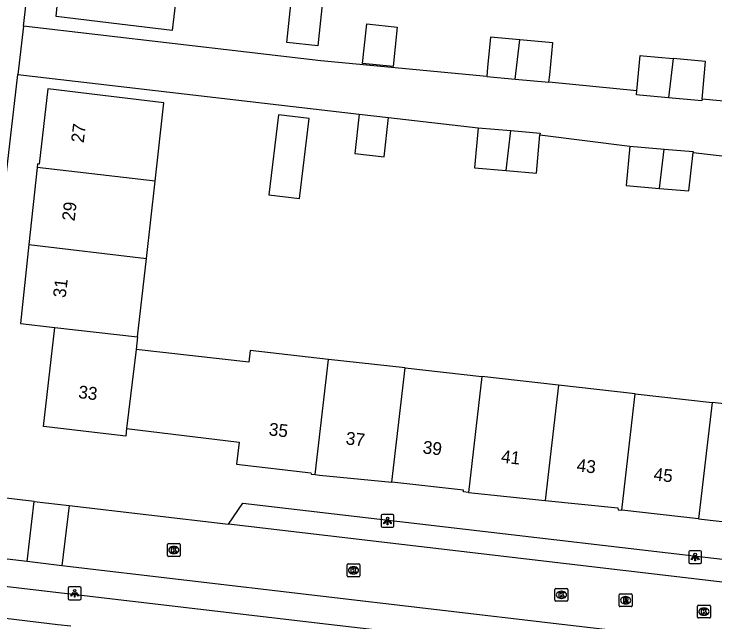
# Model space of a CAD drawing. Extents: x 161243 to 161752, y 384138 to 384885.
# Drawn here: x 161353.3 to 161408.1, y 384500.2 to 384547.7 of the extents above; entities that cross this region are included whole.
import ezdxf

# ---------------------------------------------------------------- set-up
doc = ezdxf.new("R2010")
doc.units = 0
for name, color, linetype in [('IMGEO_Kolk', 7, 'Continuous'), ('IMGEO_Lichtpunt', 7, 'Continuous'), ('IMGEO_Pand', 7, 'Continuous'), ('IMGEO_Pand_nummerreeks', 7, 'Continuous'), ('IMGEO_Parkeervlak_open', 7, 'Continuous'), ('IMGEO_Rijbaan_lokaal_open', 7, 'Continuous'), ('IMGEO_Rioolput', 7, 'Continuous'), ('IMGEO_Voetpad_open', 7, 'Continuous')]:
    doc.layers.add(name, color=color, linetype=linetype)

msp = doc.modelspace()

# ---------------------------------------------------------------- linework, layer by layer
at = {"layer": 'IMGEO_Kolk'}
for p, q in [((161365.337, 384505.38), (161365.337, 384506.232)), ((161365.412, 384506.306), (161366.264, 384506.306)), ((161365.825, 384506.086), (161365.85, 384506.086)), ((161366.338, 384506.232), (161366.338, 384505.38)), ((161366.264, 384505.306), (161365.412, 384505.306)), ((161365.848, 384505.526), (161365.823, 384505.526)), ((161379.458, 384504.718), (161380.31, 384504.718)), ((161379.383, 384503.792), (161379.383, 384504.644)), ((161379.871, 384504.498), (161379.896, 384504.498)), ((161380.384, 384504.644), (161380.384, 384503.792)), ((161380.31, 384503.718), (161379.458, 384503.718)), ((161379.894, 384503.938), (161379.869, 384503.938)), ((161395.629, 384501.882), (161395.629, 384502.734)), ((161395.704, 384502.808), (161396.556, 384502.808)), ((161396.117, 384502.588), (161396.142, 384502.588)), ((161396.63, 384502.734), (161396.63, 384501.882)), ((161396.14, 384502.028), (161396.115, 384502.028)), ((161396.556, 384501.808), (161395.704, 384501.808)), ((161406.773, 384500.574), (161406.773, 384501.426)), ((161406.848, 384501.5), (161407.7, 384501.5)), ((161407.774, 384501.426), (161407.774, 384500.574)), ((161407.261, 384501.28), (161407.286, 384501.28)), ((161407.7, 384500.5), (161406.848, 384500.5)), ((161407.284, 384500.72), (161407.259, 384500.72))]:
    msp.add_line(p, q, dxfattribs=at)
for points in [[(161365.337, 384505.38), (161365.337, 384506.232)], [(161365.412, 384506.306), (161366.264, 384506.306)], [(161365.658, 384506.006), (161365.781, 384506.006), (161365.781, 384505.855), (161365.911, 384506.006), (161366.075, 384506.006), (161365.929, 384505.855), (161366.082, 384505.606), (161365.93, 384505.606), (161365.845, 384505.77), (161365.781, 384505.703), (161365.781, 384505.606), (161365.658, 384505.606), (161365.658, 384506.006)], [(161366.338, 384506.232), (161366.338, 384505.38)], [(161366.264, 384505.306), (161365.412, 384505.306)], [(161379.458, 384504.718), (161380.31, 384504.718)], [(161379.383, 384503.792), (161379.383, 384504.644)], [(161379.704, 384504.418), (161379.827, 384504.418), (161379.827, 384504.267), (161379.957, 384504.418), (161380.121, 384504.418), (161379.975, 384504.267), (161380.128, 384504.018), (161379.976, 384504.018), (161379.891, 384504.182), (161379.827, 384504.115), (161379.827, 384504.018), (161379.704, 384504.018), (161379.704, 384504.418)], [(161380.384, 384504.644), (161380.384, 384503.792)], [(161380.31, 384503.718), (161379.458, 384503.718)], [(161395.629, 384501.882), (161395.629, 384502.734)], [(161395.704, 384502.808), (161396.556, 384502.808)], [(161395.95, 384502.508), (161396.073, 384502.508), (161396.073, 384502.357), (161396.203, 384502.508), (161396.367, 384502.508), (161396.221, 384502.357), (161396.374, 384502.108), (161396.222, 384502.108), (161396.137, 384502.272), (161396.073, 384502.205), (161396.073, 384502.108), (161395.95, 384502.108), (161395.95, 384502.508)], [(161396.63, 384502.734), (161396.63, 384501.882)], [(161396.556, 384501.808), (161395.704, 384501.808)], [(161406.773, 384500.574), (161406.773, 384501.426)], [(161406.848, 384501.5), (161407.7, 384501.5)], [(161407.774, 384501.426), (161407.774, 384500.574)], [(161407.094, 384501.2), (161407.217, 384501.2), (161407.217, 384501.049), (161407.347, 384501.2), (161407.511, 384501.2), (161407.365, 384501.049), (161407.518, 384500.8), (161407.366, 384500.8), (161407.281, 384500.964), (161407.217, 384500.897), (161407.217, 384500.8), (161407.094, 384500.8), (161407.094, 384501.2)], [(161407.7, 384500.5), (161406.848, 384500.5)]]:
    msp.add_lwpolyline(points, dxfattribs=at)
for centre, start, end in [((161365.414, 384506.23), 91.552, 178.448), ((161365.414, 384506.23), 91.552, 178.448), ((161366.262, 384506.23), 1.552, 88.448), ((161366.262, 384506.23), 1.552, 88.448), ((161365.414, 384505.382), 181.552, 268.448), ((161365.414, 384505.382), 181.552, 268.448), ((161366.262, 384505.382), 271.552, 358.448), ((161366.262, 384505.382), 271.552, 358.448), ((161379.46, 384504.642), 91.552, 178.448), ((161379.46, 384504.642), 91.552, 178.448), ((161380.308, 384504.642), 1.552, 88.448), ((161380.308, 384504.642), 1.552, 88.448), ((161379.46, 384503.794), 181.552, 268.448), ((161379.46, 384503.794), 181.552, 268.448), ((161380.308, 384503.794), 271.552, 358.448), ((161380.308, 384503.794), 271.552, 358.448), ((161395.706, 384502.732), 91.552, 178.448), ((161395.706, 384502.732), 91.552, 178.448), ((161396.554, 384502.732), 1.552, 88.448), ((161396.554, 384502.732), 1.552, 88.448), ((161395.706, 384501.884), 181.552, 268.448), ((161395.706, 384501.884), 181.552, 268.448), ((161396.554, 384501.884), 271.552, 358.448), ((161396.554, 384501.884), 271.552, 358.448), ((161406.85, 384501.424), 91.552, 178.448), ((161406.85, 384501.424), 91.552, 178.448), ((161407.698, 384501.424), 1.552, 88.448), ((161407.698, 384501.424), 1.552, 88.448), ((161406.85, 384500.576), 181.552, 268.448), ((161406.85, 384500.576), 181.552, 268.448), ((161407.698, 384500.576), 271.552, 358.448), ((161407.698, 384500.576), 271.552, 358.448)]:
    msp.add_arc(centre, 0.0765, start, end, dxfattribs=at)
for centre, major_axis, ratio, start_param, end_param in [((161365.824, 384505.806), (-0.387, 0.002), 0.722429, 4.712389, 7.853982), ((161365.849, 384505.806), (-0.39, 0.002), 0.717154, 1.570796, 4.712389), ((161379.87, 384504.218), (-0.387, 0.002), 0.722429, 4.712389, 7.853982), ((161379.895, 384504.218), (-0.39, 0.002), 0.717154, 1.570796, 4.712389), ((161396.116, 384502.308), (-0.387, 0.002), 0.722429, 4.712389, 7.853982), ((161396.141, 384502.308), (-0.39, 0.002), 0.717154, 1.570796, 4.712389), ((161407.26, 384501), (-0.387, 0.002), 0.722429, 4.712389, 7.853982), ((161407.285, 384501), (-0.39, 0.002), 0.717154, 1.570796, 4.712389)]:
    msp.add_ellipse(centre, major_axis=major_axis, ratio=ratio, start_param=start_param, end_param=end_param, dxfattribs=at)
at = {"layer": 'IMGEO_Lichtpunt'}
for p, q in [((161382.952, 384508.578), (161382.144, 384508.578)), ((161382.952, 384508.578), (161382.144, 384508.578)), ((161382.05, 384508.483), (161382.05, 384507.676)), ((161382.05, 384508.483), (161382.05, 384507.676)), ((161383.046, 384507.676), (161383.046, 384508.483)), ((161383.046, 384507.676), (161383.046, 384508.483)), ((161382.144, 384507.582), (161382.952, 384507.582)), ((161382.144, 384507.582), (161382.952, 384507.582)), ((161406.083, 384505.663), (161406.083, 384504.856)), ((161406.083, 384505.663), (161406.083, 384504.856)), ((161406.985, 384505.758), (161406.177, 384505.758)), ((161406.985, 384505.758), (161406.177, 384505.758)), ((161407.079, 384504.856), (161407.079, 384505.663)), ((161407.079, 384504.856), (161407.079, 384505.663)), ((161406.177, 384504.762), (161406.985, 384504.762)), ((161406.177, 384504.762), (161406.985, 384504.762)), ((161357.591, 384502.83), (161357.591, 384502.023)), ((161357.591, 384502.83), (161357.591, 384502.023)), ((161358.493, 384502.925), (161357.685, 384502.925)), ((161358.493, 384502.925), (161357.685, 384502.925)), ((161358.587, 384502.023), (161358.587, 384502.83)), ((161358.587, 384502.023), (161358.587, 384502.83)), ((161357.685, 384501.929), (161358.493, 384501.929)), ((161357.685, 384501.929), (161358.493, 384501.929))]:
    msp.add_line(p, q, dxfattribs=at)
for points in [[(161382.424, 384508.147), (161382.463, 384508.119), (161382.275, 384507.857), (161382.237, 384507.884), (161382.424, 384508.147)], [(161382.526, 384508.099), (161382.573, 384508.099), (161382.573, 384507.777), (161382.526, 384507.777), (161382.526, 384508.099)], [(161382.636, 384508.119), (161382.674, 384508.146), (161382.861, 384507.884), (161382.822, 384507.856), (161382.636, 384508.119)], [(161406.457, 384505.327), (161406.496, 384505.299), (161406.308, 384505.037), (161406.27, 384505.064), (161406.457, 384505.327)], [(161406.559, 384505.279), (161406.606, 384505.279), (161406.606, 384504.957), (161406.559, 384504.957), (161406.559, 384505.279)], [(161406.669, 384505.299), (161406.707, 384505.326), (161406.894, 384505.064), (161406.855, 384505.036), (161406.669, 384505.299)], [(161357.965, 384502.494), (161358.004, 384502.466), (161357.816, 384502.204), (161357.778, 384502.231), (161357.965, 384502.494)], [(161358.177, 384502.466), (161358.215, 384502.493), (161358.402, 384502.231), (161358.363, 384502.203), (161358.177, 384502.466)], [(161358.067, 384502.446), (161358.114, 384502.446), (161358.114, 384502.124), (161358.067, 384502.124), (161358.067, 384502.446)]]:
    msp.add_lwpolyline(points, dxfattribs=at)
for centre in [(161382.549, 384508.281), (161406.582, 384505.461), (161358.09, 384502.628)]:
    msp.add_circle(centre, 0.0994, dxfattribs=at)
for centre, start, end in [((161382.144, 384508.483), 90, 180), ((161382.144, 384508.483), 90, 180), ((161382.952, 384508.483), 0, 90), ((161382.952, 384508.483), 0, 90), ((161382.144, 384507.676), 180, 270), ((161382.144, 384507.676), 180, 270), ((161382.952, 384507.676), 270, 0), ((161382.952, 384507.676), 270, 360), ((161406.177, 384505.663), 90, 180), ((161406.177, 384505.663), 90, 180), ((161406.985, 384505.663), 0, 90), ((161406.985, 384505.663), 0, 90), ((161406.177, 384504.856), 180, 270), ((161406.177, 384504.856), 180, 270), ((161406.985, 384504.856), 270, 0), ((161406.985, 384504.856), 270, 360), ((161357.685, 384502.83), 90, 180), ((161357.685, 384502.83), 90, 180), ((161358.493, 384502.83), 0, 90), ((161358.493, 384502.83), 0, 90), ((161357.685, 384502.023), 180, 270), ((161357.685, 384502.023), 180, 270), ((161358.493, 384502.023), 270, 0), ((161358.493, 384502.023), 270, 360)]:
    msp.add_arc(centre, 0.0946, start, end, dxfattribs=at)
at = {"layer": 'IMGEO_Pand'}
for points in [[(161366.438, 384552.56), (161365.715, 384546.372), (161361.603, 384546.876), (161356.64, 384547.484), (161357.225, 384553.321), (161357.263, 384553.636)], [(161374.67, 384545.446), (161375.302, 384551.397), (161377.728, 384551.139), (161377.098, 384545.197), (161374.67, 384545.446)], [(161380.915, 384546.899), (161383.297, 384546.65), (161382.973, 384543.56), (161380.592, 384543.81), (161380.915, 384546.899)], [(161392.883, 384545.649), (161390.582, 384545.866), (161390.36, 384543.501), (161390.293, 384542.794)], [(161392.525, 384542.584), (161392.883, 384545.649)], [(161395.161, 384542.336), (161395.217, 384542.927), (161395.45, 384545.408), (161392.883, 384545.649)], [(161402.036, 384541.672), (161402.295, 384544.437), (161402.53, 384544.415), (161404.855, 384544.197)], [(161404.855, 384544.197), (161404.496, 384541.131)], [(161407.123, 384541.032), (161407.398, 384543.958), (161404.855, 384544.197)], [(161390.293, 384542.794), (161392.525, 384542.584)], [(161392.525, 384542.584), (161395.161, 384542.336)], [(161364.373, 384534.605), (161365.062, 384540.738), (161360.954, 384541.232), (161355.989, 384541.828), (161355.319, 384535.95), (161355.195, 384535.982), (161355.163, 384535.687)], [(161404.496, 384541.131), (161402.241, 384541.343), (161402.007, 384541.365), (161402.036, 384541.672)], [(161407.123, 384541.032), (161407.109, 384540.886), (161404.496, 384541.131)], [(161373.265, 384533.537), (161375.67, 384533.25), (161376.416, 384539.512), (161374.01, 384539.798), (161373.265, 384533.537)], [(161380.337, 384539.851), (161379.995, 384536.783), (161382.266, 384536.529), (161382.609, 384539.597)], [(161380.337, 384539.851), (161382.609, 384539.597)], [(161389.625, 384538.791), (161389.352, 384535.651), (161391.807, 384535.437)], [(161389.625, 384538.791), (161392.174, 384538.569)], [(161391.807, 384535.437), (161392.174, 384538.569)], [(161391.807, 384535.437), (161394.187, 384535.23), (161394.449, 384538.235)], [(161392.174, 384538.569), (161394.461, 384538.369), (161394.449, 384538.235)], [(161401.474, 384537.359), (161401.206, 384534.28), (161403.791, 384534.055)], [(161401.474, 384537.359), (161404.151, 384537.125)], [(161403.791, 384534.055), (161404.151, 384537.125)], [(161404.151, 384537.125), (161406.44, 384536.926), (161406.432, 384536.854)], [(161403.791, 384534.055), (161406.08, 384533.855), (161406.432, 384536.854)], [(161355.163, 384535.687), (161354.513, 384529.66)], [(161364.373, 384534.605), (161355.163, 384535.687)], [(161363.697, 384528.581), (161364.373, 384534.605)], [(161354.513, 384529.66), (161353.849, 384523.505), (161356.534, 384523.195)], [(161354.513, 384529.66), (161363.697, 384528.581)], [(161363.009, 384522.448), (161363.697, 384528.581)], [(161362.13, 384515.29), (161362.078, 384514.704), (161355.646, 384515.453), (161356.534, 384523.195)], [(161356.534, 384523.195), (161363.009, 384522.448)], [(161363.009, 384522.448), (161362.9, 384521.481)], [(161362.9, 384521.481), (161362.13, 384515.29)], [(161377.931, 384520.699), (161371.808, 384521.386), (161371.708, 384520.492), (161362.9, 384521.481)], [(161376.875, 384511.701), (161377.931, 384520.699)], [(161383.926, 384520.026), (161377.931, 384520.699)], [(161382.88, 384511.115), (161383.926, 384520.026)], [(161383.926, 384520.026), (161389.92, 384519.353)], [(161389.92, 384519.353), (161388.859, 384510.31)], [(161395.914, 384518.68), (161389.92, 384519.353)], [(161395.914, 384518.68), (161394.858, 384509.685)], [(161401.908, 384518.007), (161395.914, 384518.68)], [(161400.842, 384508.921), (161401.908, 384518.007)], [(161401.908, 384518.007), (161407.903, 384517.334)], [(161407.903, 384517.334), (161406.836, 384508.241)], [(161413.897, 384516.661), (161407.903, 384517.334)], [(161362.13, 384515.29), (161370.953, 384514.221), (161370.746, 384512.522), (161376.552, 384511.837), (161376.584, 384511.732), (161376.875, 384511.701)], [(161376.875, 384511.701), (161377.225, 384511.664), (161382.88, 384511.115)], [(161388.859, 384510.31), (161388.492, 384510.348), (161388.492, 384510.475), (161382.88, 384511.115)], [(161388.859, 384510.31), (161394.858, 384509.685)], [(161394.858, 384509.685), (161400.554, 384509.091), (161400.579, 384508.951), (161400.842, 384508.921)], [(161406.836, 384508.241), (161400.842, 384508.921)], [(161406.836, 384508.241), (161412.83, 384507.56)], [(161351.799, 384500.579), (161356.763, 384500), (161357.799, 384499.879)]]:
    msp.add_lwpolyline(points, dxfattribs=at)
at = {"layer": 'IMGEO_Parkeervlak_open'}
msp.add_lwpolyline([(161370.122, 384507.816), (161371.245, 384509.461), (161423.885, 384503.32), (161424.463, 384501.437)], dxfattribs=at)
at = {"layer": 'IMGEO_Rijbaan_lokaal_open'}
for points in [[(161414.97, 384570.779), (161411.359, 384540.633), (161407.123, 384541.032)], [(161354.08, 384546.72), (161353.642, 384542.948)], [(161390.293, 384542.794), (161377.34, 384544.021), (161354.08, 384546.72)], [(161353.642, 384542.948), (161380.337, 384539.851)], [(161402.036, 384541.672), (161395.161, 384542.336)], [(161382.609, 384539.597), (161389.625, 384538.791)], [(161394.449, 384538.235), (161401.474, 384537.359)], [(161406.432, 384536.854), (161419.21, 384535.381), (161421.738, 384535.09), (161421.212, 384528.819), (161423.722, 384528.608), (161426.026, 384528.384)], [(161354.929, 384509.609), (161349.844, 384510.209)], [(161354.376, 384504.9), (161354.929, 384509.609)], [(161354.929, 384509.609), (161357.65, 384509.288)], [(161357.65, 384509.288), (161357.097, 384504.581)], [(161357.65, 384509.288), (161370.122, 384507.816)], [(161424.463, 384501.437), (161370.122, 384507.816)], [(161354.376, 384504.9), (161340.82, 384506.489)], [(161357.097, 384504.581), (161354.376, 384504.9)], [(161427.321, 384496.383), (161396.178, 384500), (161357.097, 384504.581)]]:
    msp.add_lwpolyline(points, dxfattribs=at)
at = {"layer": 'IMGEO_Rioolput'}
for p, q in [((161400.653, 384501.46), (161400.653, 384502.312)), ((161400.728, 384502.386), (161401.58, 384502.386)), ((161401.141, 384502.166), (161401.166, 384502.166)), ((161401.654, 384502.312), (161401.654, 384501.46)), ((161401.164, 384501.606), (161401.139, 384501.606)), ((161401.58, 384501.386), (161400.728, 384501.386))]:
    msp.add_line(p, q, dxfattribs=at)
for points in [[(161400.653, 384501.46), (161400.653, 384502.312)], [(161400.728, 384502.386), (161401.58, 384502.386)], [(161401.242, 384502.084), (161400.99, 384502.086), (161400.99, 384501.686)], [(161401.168, 384502.005), (161401.114, 384502.005), (161401.114, 384501.924)], [(161401.654, 384502.312), (161401.654, 384501.46)], [(161400.99, 384501.686), (161401.114, 384501.686), (161401.114, 384501.848), (161401.125, 384501.848)], [(161401.114, 384501.924), (161401.166, 384501.924)], [(161401.172, 384501.819), (161401.243, 384501.686), (161401.383, 384501.686), (161401.318, 384501.812)], [(161401.58, 384501.386), (161400.728, 384501.386)]]:
    msp.add_lwpolyline(points, dxfattribs=at)
for centre, radius, start, end in [((161400.73, 384502.31), 0.0765, 91.552, 178.448), ((161400.73, 384502.31), 0.0765, 91.552, 178.448), ((161401.174, 384501.909), 0.0964, 77.0061, 93.1865), ((161401.188, 384501.966), 0.0378, 276.6634, 79.6772), ((161401.241, 384501.974), 0.109, 350.3612, 89.416), ((161401.239, 384501.974), 0.112, 277.5842, 350.9817), ((161401.578, 384502.31), 0.0765, 1.552, 88.448), ((161401.578, 384502.31), 0.0765, 1.552, 88.448), ((161400.73, 384501.462), 0.0765, 181.552, 268.448), ((161400.73, 384501.462), 0.0765, 181.552, 268.448), ((161401.124, 384501.795), 0.0533, 26.0293, 88.6989), ((161401.15, 384502.113), 0.19, 274.7715, 282.9687), ((161401.223, 384501.759), 0.108, 29.5134, 73.7905), ((161401.578, 384501.462), 0.0765, 271.552, 358.448), ((161401.578, 384501.462), 0.0765, 271.552, 358.448)]:
    msp.add_arc(centre, radius, start, end, dxfattribs=at)
for centre, major_axis, ratio, start_param, end_param in [((161401.14, 384501.886), (-0.387, 0.002), 0.722429, 4.712389, 7.853982), ((161401.165, 384501.886), (-0.39, 0.002), 0.717154, 1.570796, 4.712389)]:
    msp.add_ellipse(centre, major_axis=major_axis, ratio=ratio, start_param=start_param, end_param=end_param, dxfattribs=at)
at = {"layer": 'IMGEO_Voetpad_open'}
for points in [[(161354.08, 384546.72), (161357.485, 384576.07)], [(161349.844, 384510.209), (161353.642, 384542.948)], [(161395.453, 384497.957), (161377.935, 384500), (161341.704, 384504.225)]]:
    msp.add_lwpolyline(points, dxfattribs=at)

# ---------------------------------------------------------------- texts
at = {"layer": 'IMGEO_Pand_nummerreeks'}
for s, rotation, p in [('27', 83.3384, (161358.795, 384537.573)), ('29', 83.3384, (161358.081, 384531.465)), ('31', 83.3384, (161357.381, 384525.469)), ('33', 353.3579, (161358.332, 384517.677)), ('35', 353.3314, (161373.225, 384514.769)), ('37', 353.3314, (161379.24, 384514.066)), ('39', 353.3314, (161385.254, 384513.362)), ('41', 353.3314, (161391.381, 384512.646)), ('43', 353.3314, (161397.284, 384511.956)), ('45', 353.3314, (161403.298, 384511.253))]:
    msp.add_text(s, height=1, rotation=rotation, dxfattribs=at).set_placement(p)

doc.saveas('drawing.dxf')
